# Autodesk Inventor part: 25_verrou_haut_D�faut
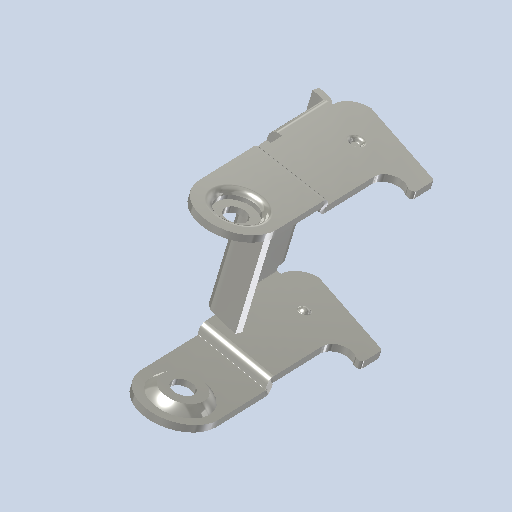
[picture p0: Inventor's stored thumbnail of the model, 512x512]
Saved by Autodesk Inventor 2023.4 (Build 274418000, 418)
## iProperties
Created: 2011-01
Part Number: 25_verrou_haut_D�faut
Document SubType Name: Modeling
Designer: eric
Density: 1 g/cm^3
Mass: 9.60647 g
Surface Area: 107.796 cm^2
Volume: 9.60647 cm^3
Material: Générique
Appearance: Nitrure de silicium - Poli
Author: eric
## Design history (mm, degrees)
node "Base1"
sketch "Esquisse1"
  geometry: C1 r 3 at (-0.001, -0.006) reference; C2 r 5.458 at (-0.001, -0.006)
  constraints: 1 centre point, 1 coincident
extrude "Extrusion1" cut sketch "Esquisse1" extent not by distance; stored distance "d0" = 10; taper "d1" = 0 deg
node "Corps solides"
node "Corps surfaciques"
node "Solide1"
